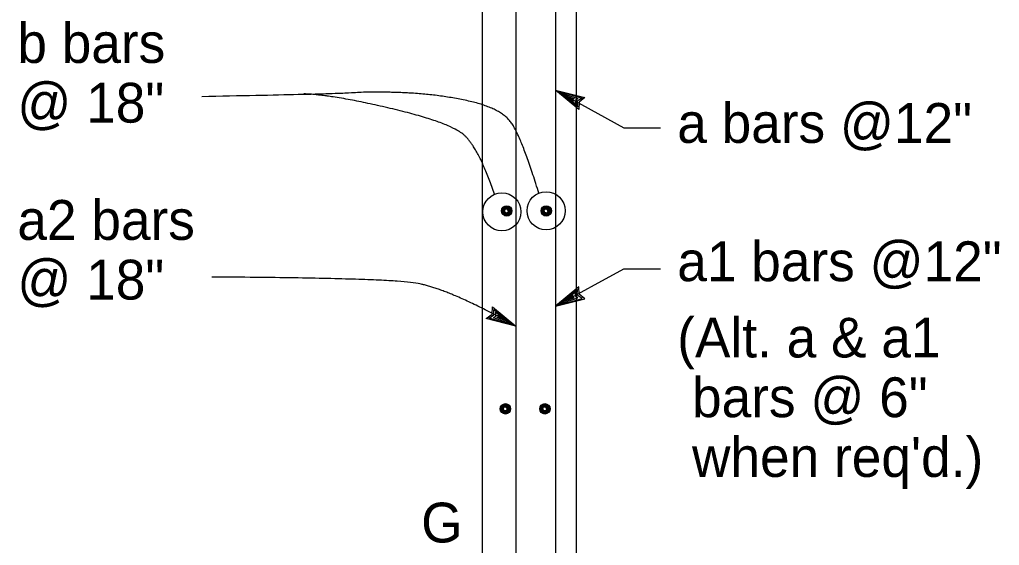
# Model space of a CAD drawing. Extents: x -0.08 to 2.83, y -0.03 to 1.92.
# Drawn here: x 1.1982 to 1.5188, y 0.4851 to 0.6571 of the extents above; entities that cross this region are included whole.
import ezdxf

# ---------------------------------------------------------------- set-up
doc = ezdxf.new("R2010")
doc.units = 0
for name, color, linetype in [('50', 7, 'Continuous'), ('51', 7, 'Continuous'), ('55', 7, 'Continuous'), ('57', 7, 'Continuous')]:
    doc.layers.add(name, color=color, linetype=linetype)

msp = doc.modelspace()

# ---------------------------------------------------------------- linework, layer by layer
at = {"layer": '50'}
for p, q in [((1.34968, 0.37752), (1.34968, 0.72906)), ((1.38033, 0.72906), (1.38033, 0.37752))]:
    msp.add_line(p, q, dxfattribs=at)
at = {"layer": '51'}
for p, q in [((1.36058, 0.72394), (1.36058, 0.4673)), ((1.37352, 0.72394), (1.37352, 0.50937)), ((1.37352, 0.50937), (1.37352, 0.46972))]:
    msp.add_line(p, q, dxfattribs=at)
for points in [[(1.356, 0.59466), (1.35622, 0.59531), (1.35668, 0.5958), (1.35727, 0.59607), (1.35784, 0.59607), (1.35829, 0.59593), (1.35866, 0.59564), (1.35896, 0.59523), (1.3591, 0.59483), (1.35914, 0.59428), (1.35903, 0.59376), (1.35876, 0.5934), (1.35833, 0.59308), (1.35784, 0.59291), (1.35722, 0.59291), (1.35673, 0.59316), (1.35637, 0.59346), (1.35617, 0.59379), (1.35604, 0.59419), (1.35605, 0.59457), (1.35619, 0.59496), (1.35638, 0.59534), (1.35668, 0.59566), (1.35696, 0.59586), (1.35723, 0.59596), (1.35751, 0.59598), (1.35789, 0.59598), (1.35821, 0.59586), (1.35847, 0.59564), (1.35869, 0.59545), (1.35889, 0.59515), (1.35899, 0.59477), (1.35903, 0.59438), (1.35898, 0.59405), (1.35886, 0.59367), (1.35871, 0.59348), (1.35844, 0.59329), (1.35819, 0.59313), (1.35789, 0.59304), (1.35754, 0.59299), (1.3571, 0.59311), (1.35673, 0.59329), (1.35644, 0.59354), (1.35622, 0.59398), (1.35615, 0.59438), (1.35624, 0.59477), (1.35641, 0.59515), (1.35667, 0.59551), (1.3569, 0.59572), (1.3572, 0.59583), (1.35759, 0.59588), (1.35795, 0.5958), (1.35821, 0.59566), (1.35851, 0.59539), (1.35875, 0.59504), (1.35884, 0.59468), (1.35887, 0.59428), (1.35883, 0.59395), (1.35861, 0.59354), (1.35833, 0.59332), (1.35801, 0.59321), (1.35758, 0.59313), (1.35713, 0.59324), (1.35679, 0.5934), (1.35655, 0.59362), (1.35638, 0.59392), (1.3563, 0.59419), (1.3563, 0.59455), (1.35641, 0.59483), (1.35654, 0.59509), (1.3567, 0.59531), (1.35696, 0.59561), (1.35725, 0.59574), (1.35759, 0.59577), (1.35788, 0.59569), (1.35826, 0.59541), (1.35851, 0.59509), (1.35869, 0.59471), (1.35871, 0.5943), (1.35864, 0.594), (1.35859, 0.59379), (1.35834, 0.59348), (1.35811, 0.59337), (1.35771, 0.59324), (1.35729, 0.59332), (1.35691, 0.59348), (1.35664, 0.5937), (1.35646, 0.59403), (1.35639, 0.59433), (1.35647, 0.59468), (1.35668, 0.59506), (1.35688, 0.59536), (1.3571, 0.59561), (1.35743, 0.59569), (1.35758, 0.59564), (1.35781, 0.59561), (1.35801, 0.59545), (1.35828, 0.59518), (1.35839, 0.59501), (1.35851, 0.59483), (1.35857, 0.59463)], [(1.35857, 0.59463), (1.35848, 0.59413), (1.35844, 0.59379), (1.35826, 0.59362), (1.35801, 0.59346), (1.35771, 0.5934), (1.35738, 0.5934), (1.35707, 0.59351), (1.35683, 0.5937), (1.35665, 0.59392), (1.35653, 0.59416), (1.35659, 0.59457), (1.35673, 0.59493), (1.35691, 0.59518), (1.35711, 0.59548), (1.3574, 0.59558), (1.35771, 0.59545), (1.35786, 0.59534), (1.35808, 0.59515), (1.35821, 0.59498), (1.35833, 0.59477), (1.35837, 0.59457), (1.35839, 0.59438), (1.35836, 0.59419), (1.35828, 0.59389), (1.35822, 0.59376), (1.35813, 0.59367), (1.35795, 0.59356), (1.35783, 0.59351), (1.35767, 0.59351), (1.35748, 0.59351), (1.35736, 0.59351), (1.3572, 0.59356), (1.35705, 0.59367), (1.35676, 0.59405), (1.35668, 0.59428), (1.3567, 0.59452), (1.35678, 0.59477), (1.35685, 0.59491), (1.35698, 0.59512), (1.3571, 0.59523), (1.35725, 0.59536), (1.35741, 0.59541), (1.35769, 0.59534), (1.35777, 0.59528), (1.35789, 0.59515), (1.35801, 0.59501), (1.35811, 0.59488), (1.35816, 0.59473), (1.35823, 0.59463), (1.35828, 0.59449), (1.35829, 0.59441), (1.35823, 0.59424), (1.35821, 0.59413), (1.35816, 0.59403), (1.35808, 0.59389), (1.35798, 0.59376), (1.35788, 0.5937), (1.35769, 0.59365), (1.35754, 0.59365), (1.35738, 0.59365), (1.35725, 0.59372), (1.3571, 0.59384), (1.35698, 0.59398), (1.35691, 0.59411), (1.35685, 0.59424), (1.35681, 0.59438), (1.3569, 0.59452), (1.35696, 0.59466), (1.35703, 0.59488), (1.35711, 0.59501), (1.35721, 0.59512), (1.35735, 0.59518), (1.35754, 0.59518), (1.35771, 0.59509), (1.35779, 0.59504), (1.35791, 0.59488), (1.35798, 0.59477), (1.35803, 0.59468), (1.35808, 0.59457), (1.35809, 0.59447), (1.35811, 0.59433), (1.35809, 0.59422), (1.35808, 0.59416), (1.35801, 0.59405), (1.35793, 0.594), (1.35789, 0.59395), (1.35786, 0.59389), (1.35781, 0.59384), (1.35771, 0.59381), (1.35762, 0.59381), (1.35748, 0.59384), (1.35738, 0.59384), (1.35727, 0.59389), (1.35717, 0.59395), (1.35707, 0.59403), (1.35703, 0.59411), (1.35702, 0.59422), (1.35698, 0.59435), (1.35696, 0.59444), (1.35702, 0.59455)], [(1.36894, 0.59466), (1.36916, 0.59531), (1.36962, 0.5958), (1.37021, 0.59607), (1.37078, 0.59607), (1.37123, 0.59593), (1.37161, 0.59564), (1.3719, 0.59523), (1.37205, 0.59483), (1.37209, 0.59428), (1.37197, 0.59376), (1.37171, 0.5934), (1.37127, 0.59308), (1.37078, 0.59291), (1.37017, 0.59291), (1.36968, 0.59316), (1.36931, 0.59346), (1.36911, 0.59379), (1.36898, 0.59419), (1.36899, 0.59457), (1.36914, 0.59496), (1.36932, 0.59534), (1.36962, 0.59566), (1.36991, 0.59586), (1.37018, 0.59596), (1.37046, 0.59598), (1.37083, 0.59598), (1.37115, 0.59586), (1.37141, 0.59564), (1.37163, 0.59545), (1.37183, 0.59515), (1.37194, 0.59477), (1.37197, 0.59438), (1.37193, 0.59405), (1.37181, 0.59367), (1.37166, 0.59348), (1.37138, 0.59329), (1.37114, 0.59313), (1.37083, 0.59304), (1.37048, 0.59299), (1.37004, 0.59311), (1.36968, 0.59329), (1.36939, 0.59354), (1.36916, 0.59398), (1.36909, 0.59438), (1.36919, 0.59477), (1.36935, 0.59515), (1.36961, 0.59551), (1.36984, 0.59572), (1.37014, 0.59583), (1.37054, 0.59588), (1.37089, 0.5958), (1.37115, 0.59566), (1.37145, 0.59539), (1.37169, 0.59504), (1.37179, 0.59468), (1.37182, 0.59428), (1.37178, 0.59395), (1.37156, 0.59354), (1.37127, 0.59332), (1.37096, 0.59321), (1.37052, 0.59313), (1.37008, 0.59324), (1.36974, 0.5934), (1.3695, 0.59362), (1.36932, 0.59392), (1.36924, 0.59419), (1.36924, 0.59455), (1.36935, 0.59483), (1.36949, 0.59509), (1.36965, 0.59531), (1.36991, 0.59561), (1.37019, 0.59574), (1.37054, 0.59577), (1.37083, 0.59569), (1.3712, 0.59541), (1.37145, 0.59509), (1.37163, 0.59471), (1.37166, 0.5943), (1.37159, 0.594), (1.37153, 0.59379), (1.37128, 0.59348), (1.37105, 0.59337), (1.37066, 0.59324), (1.37024, 0.59332), (1.36986, 0.59348), (1.36958, 0.5937), (1.3694, 0.59403), (1.36934, 0.59433), (1.36942, 0.59468), (1.36962, 0.59506), (1.36982, 0.59536), (1.37004, 0.59561), (1.37037, 0.59569), (1.37052, 0.59564), (1.37076, 0.59561), (1.37094, 0.59545), (1.37122, 0.59518), (1.37134, 0.59501), (1.37145, 0.59483), (1.37152, 0.59463)], [(1.37152, 0.59463), (1.37143, 0.59413), (1.37138, 0.59379), (1.3712, 0.59362), (1.37096, 0.59346), (1.37066, 0.5934), (1.37033, 0.5934), (1.37002, 0.59351), (1.36977, 0.5937), (1.3696, 0.59392), (1.36947, 0.59416), (1.36953, 0.59457), (1.36968, 0.59493), (1.36986, 0.59518), (1.37006, 0.59548), (1.37035, 0.59558), (1.37066, 0.59545), (1.3708, 0.59534), (1.37101, 0.59515), (1.37115, 0.59498), (1.37127, 0.59477), (1.37131, 0.59457), (1.37134, 0.59438), (1.3713, 0.59419), (1.37122, 0.59389), (1.37116, 0.59376), (1.37108, 0.59367), (1.37089, 0.59356), (1.37078, 0.59351), (1.37062, 0.59351), (1.37042, 0.59351), (1.3703, 0.59351), (1.37014, 0.59356), (1.36999, 0.59367), (1.36971, 0.59405), (1.36962, 0.59428), (1.36964, 0.59452), (1.36971, 0.59477), (1.36979, 0.59491), (1.36993, 0.59512), (1.37004, 0.59523), (1.37019, 0.59536), (1.37036, 0.59541), (1.37063, 0.59534), (1.37072, 0.59528), (1.37083, 0.59515), (1.37096, 0.59501), (1.37105, 0.59488), (1.37111, 0.59473), (1.37118, 0.59463), (1.37122, 0.59449), (1.37123, 0.59441), (1.37118, 0.59424), (1.37115, 0.59413), (1.37111, 0.59403), (1.37103, 0.59389), (1.37093, 0.59376), (1.37083, 0.5937), (1.37063, 0.59365), (1.37048, 0.59365), (1.37033, 0.59365), (1.37019, 0.59372), (1.37004, 0.59384), (1.36993, 0.59398), (1.36986, 0.59411), (1.36979, 0.59424), (1.36976, 0.59438), (1.36984, 0.59452), (1.36989, 0.59466), (1.36998, 0.59488), (1.37006, 0.59501), (1.37015, 0.59512), (1.37029, 0.59518), (1.37048, 0.59518), (1.37066, 0.59509), (1.37073, 0.59504), (1.37086, 0.59488), (1.37093, 0.59477), (1.37098, 0.59468), (1.37101, 0.59457), (1.37104, 0.59447), (1.37105, 0.59433), (1.37104, 0.59422), (1.37103, 0.59416), (1.37094, 0.59405), (1.37088, 0.594), (1.37083, 0.59395), (1.37081, 0.59389), (1.37076, 0.59384), (1.37066, 0.59381), (1.37057, 0.59381), (1.37042, 0.59384), (1.37032, 0.59384), (1.37021, 0.59389), (1.37012, 0.59395), (1.37002, 0.59403), (1.36998, 0.59411), (1.36997, 0.59422), (1.36993, 0.59435), (1.36991, 0.59444), (1.36997, 0.59455)], [(1.35558, 0.52993), (1.35579, 0.53059), (1.35626, 0.53108), (1.35685, 0.53135), (1.35741, 0.53135), (1.35786, 0.53121), (1.35823, 0.53092), (1.35853, 0.53051), (1.35869, 0.5301), (1.35872, 0.52955), (1.3586, 0.52904), (1.35834, 0.52868), (1.35791, 0.52836), (1.35741, 0.52819), (1.3568, 0.52819), (1.35631, 0.52843), (1.35594, 0.52874), (1.35574, 0.52907), (1.35561, 0.52947), (1.35563, 0.52986), (1.35577, 0.53023), (1.35596, 0.53061), (1.35626, 0.53094), (1.35654, 0.53113), (1.35681, 0.53124), (1.35709, 0.53127), (1.35747, 0.53127), (1.35779, 0.53113), (1.35804, 0.53092), (1.35826, 0.53072), (1.35847, 0.53043), (1.35857, 0.53004), (1.3586, 0.52966), (1.35856, 0.52933), (1.35844, 0.52895), (1.35829, 0.52876), (1.35801, 0.52857), (1.35777, 0.52841), (1.35747, 0.52832), (1.35711, 0.52827), (1.35668, 0.52838), (1.35631, 0.52857), (1.35602, 0.52882), (1.35579, 0.52925), (1.35573, 0.52966), (1.35582, 0.53004), (1.35599, 0.53043), (1.35624, 0.53077), (1.35647, 0.53099), (1.35678, 0.53111), (1.35717, 0.53116), (1.35753, 0.53108), (1.35779, 0.53094), (1.35808, 0.53067), (1.35833, 0.53031), (1.35842, 0.52996), (1.35845, 0.52955), (1.35841, 0.52923), (1.35819, 0.52882), (1.35791, 0.5286), (1.35759, 0.52848), (1.35716, 0.52841), (1.3567, 0.52852), (1.35637, 0.52868), (1.35613, 0.5289), (1.35596, 0.5292), (1.35587, 0.52947), (1.35587, 0.52982), (1.35599, 0.5301), (1.35612, 0.53037), (1.35628, 0.53059), (1.35654, 0.53089), (1.35683, 0.53102), (1.35717, 0.53105), (1.35746, 0.53097), (1.35784, 0.5307), (1.35808, 0.53037), (1.35826, 0.52999), (1.35829, 0.52958), (1.35822, 0.52928), (1.35816, 0.52907), (1.35791, 0.52876), (1.35769, 0.52865), (1.35729, 0.52852), (1.35687, 0.5286), (1.35649, 0.52876), (1.35622, 0.52897), (1.35604, 0.52931), (1.35597, 0.5296), (1.35605, 0.52996), (1.35626, 0.53034), (1.35646, 0.53064), (1.35668, 0.53089), (1.35701, 0.53097), (1.35716, 0.53092), (1.35738, 0.53089), (1.35758, 0.53072), (1.35786, 0.53045), (1.35798, 0.53028), (1.35808, 0.5301), (1.35815, 0.52991)], [(1.35815, 0.52991), (1.35806, 0.52942), (1.35801, 0.52907), (1.35784, 0.5289), (1.35759, 0.52874), (1.35729, 0.52868), (1.35696, 0.52868), (1.35665, 0.52879), (1.35641, 0.52897), (1.35623, 0.5292), (1.35611, 0.52944), (1.35617, 0.52986), (1.35631, 0.53021), (1.35649, 0.53045), (1.3567, 0.53075), (1.35698, 0.53087), (1.35729, 0.53072), (1.35743, 0.53061), (1.35764, 0.53043), (1.35779, 0.53026), (1.35791, 0.53004), (1.35795, 0.52986), (1.35798, 0.52966), (1.35793, 0.52947), (1.35786, 0.52917), (1.3578, 0.52904), (1.35771, 0.52895), (1.35753, 0.52885), (1.3574, 0.52879), (1.35725, 0.52879), (1.35706, 0.52879), (1.35694, 0.52879), (1.35678, 0.52885), (1.35662, 0.52895), (1.35634, 0.52933), (1.35626, 0.52955), (1.35628, 0.5298), (1.35635, 0.53004), (1.35643, 0.53017), (1.35655, 0.5304), (1.35668, 0.53051), (1.35683, 0.53064), (1.35699, 0.5307), (1.35727, 0.53061), (1.35735, 0.53056), (1.35747, 0.53043), (1.35759, 0.53028), (1.35769, 0.53015), (1.35774, 0.53002), (1.35781, 0.52991), (1.35786, 0.52977), (1.35786, 0.52969), (1.35781, 0.52952), (1.35779, 0.52942), (1.35774, 0.52931), (1.35766, 0.52917), (1.35756, 0.52904), (1.35746, 0.52897), (1.35727, 0.52892), (1.35711, 0.52892), (1.35696, 0.52892), (1.35683, 0.52901), (1.35668, 0.52912), (1.35655, 0.52925), (1.35649, 0.52939), (1.35643, 0.52952), (1.35639, 0.52966), (1.35647, 0.5298), (1.35653, 0.52993), (1.35662, 0.53015), (1.3567, 0.53028), (1.35679, 0.5304), (1.35693, 0.53045), (1.35711, 0.53045), (1.35729, 0.53037), (1.35736, 0.53031), (1.3575, 0.53015), (1.35756, 0.53004), (1.35761, 0.52996), (1.35764, 0.52986), (1.35767, 0.52975), (1.35769, 0.5296), (1.35767, 0.5295), (1.35766, 0.52944), (1.35758, 0.52933), (1.35751, 0.52928), (1.35747, 0.52923), (1.35744, 0.52917), (1.35738, 0.52912), (1.35729, 0.52909), (1.3572, 0.52909), (1.35706, 0.52912), (1.35696, 0.52912), (1.35685, 0.52917), (1.35674, 0.52923), (1.35665, 0.52931), (1.35662, 0.52939), (1.3566, 0.5295), (1.35655, 0.52963), (1.35654, 0.52972), (1.3566, 0.52982)], [(1.36852, 0.52993), (1.36874, 0.53059), (1.3692, 0.53108), (1.36979, 0.53135), (1.37036, 0.53135), (1.37081, 0.53121), (1.37118, 0.53092), (1.37148, 0.53051), (1.37163, 0.5301), (1.37167, 0.52955), (1.37154, 0.52904), (1.37128, 0.52868), (1.37085, 0.52836), (1.37036, 0.52819), (1.36974, 0.52819), (1.36926, 0.52843), (1.36889, 0.52874), (1.36869, 0.52907), (1.36856, 0.52947), (1.36857, 0.52986), (1.36872, 0.53023), (1.36891, 0.53061), (1.3692, 0.53094), (1.36949, 0.53113), (1.36976, 0.53124), (1.37004, 0.53127), (1.37041, 0.53127), (1.37073, 0.53113), (1.37099, 0.53092), (1.3712, 0.53072), (1.37141, 0.53043), (1.37152, 0.53004), (1.37154, 0.52966), (1.37151, 0.52933), (1.37138, 0.52895), (1.37123, 0.52876), (1.37096, 0.52857), (1.37072, 0.52841), (1.37041, 0.52832), (1.37006, 0.52827), (1.36962, 0.52838), (1.36926, 0.52857), (1.36897, 0.52882), (1.36874, 0.52925), (1.36867, 0.52966), (1.36877, 0.53004), (1.36893, 0.53043), (1.36919, 0.53077), (1.36942, 0.53099), (1.36971, 0.53111), (1.37012, 0.53116), (1.37047, 0.53108), (1.37073, 0.53094), (1.37103, 0.53067), (1.37127, 0.53031), (1.37136, 0.52996), (1.3714, 0.52955), (1.37136, 0.52923), (1.37114, 0.52882), (1.37085, 0.5286), (1.37054, 0.52848), (1.3701, 0.52841), (1.36965, 0.52852), (1.36931, 0.52868), (1.36908, 0.5289), (1.36891, 0.5292), (1.36882, 0.52947), (1.36882, 0.52982), (1.36893, 0.5301), (1.36906, 0.53037), (1.36923, 0.53059), (1.36949, 0.53089), (1.36977, 0.53102), (1.37012, 0.53105), (1.3704, 0.53097), (1.37078, 0.5307), (1.37103, 0.53037), (1.3712, 0.52999), (1.37123, 0.52958), (1.37116, 0.52928), (1.37111, 0.52907), (1.37086, 0.52876), (1.37063, 0.52865), (1.37024, 0.52852), (1.36982, 0.5286), (1.36943, 0.52876), (1.36916, 0.52897), (1.36898, 0.52931), (1.36892, 0.5296), (1.36899, 0.52996), (1.3692, 0.53034), (1.3694, 0.53064), (1.36962, 0.53089), (1.36995, 0.53097), (1.3701, 0.53092), (1.37033, 0.53089), (1.37052, 0.53072), (1.3708, 0.53045), (1.37092, 0.53028), (1.37103, 0.5301), (1.37109, 0.52991)], [(1.37109, 0.52991), (1.371, 0.52942), (1.37096, 0.52907), (1.37078, 0.5289), (1.37054, 0.52874), (1.37024, 0.52868), (1.36991, 0.52868), (1.3696, 0.52879), (1.36935, 0.52897), (1.36918, 0.5292), (1.36906, 0.52944), (1.36911, 0.52986), (1.36926, 0.53021), (1.36943, 0.53045), (1.36964, 0.53075), (1.36993, 0.53087), (1.37024, 0.53072), (1.37037, 0.53061), (1.37059, 0.53043), (1.37073, 0.53026), (1.37085, 0.53004), (1.37089, 0.52986), (1.37092, 0.52966), (1.37088, 0.52947), (1.3708, 0.52917), (1.37074, 0.52904), (1.37066, 0.52895), (1.37047, 0.52885), (1.37035, 0.52879), (1.37019, 0.52879), (1.37, 0.52879), (1.36989, 0.52879), (1.36971, 0.52885), (1.36956, 0.52895), (1.36929, 0.52933), (1.3692, 0.52955), (1.36921, 0.5298), (1.3693, 0.53004), (1.36938, 0.53017), (1.3695, 0.5304), (1.36962, 0.53051), (1.36977, 0.53064), (1.36994, 0.5307), (1.37021, 0.53061), (1.37029, 0.53056), (1.37041, 0.53043), (1.37054, 0.53028), (1.37063, 0.53015), (1.37068, 0.53002), (1.37076, 0.52991), (1.3708, 0.52977), (1.37081, 0.52969), (1.37076, 0.52952), (1.37073, 0.52942), (1.37068, 0.52931), (1.3706, 0.52917), (1.37051, 0.52904), (1.3704, 0.52897), (1.37021, 0.52892), (1.37006, 0.52892), (1.36991, 0.52892), (1.36977, 0.52901), (1.36962, 0.52912), (1.3695, 0.52925), (1.36943, 0.52939), (1.36938, 0.52952), (1.36934, 0.52966), (1.36942, 0.5298), (1.36947, 0.52993), (1.36956, 0.53015), (1.36964, 0.53028), (1.36974, 0.5304), (1.36987, 0.53045), (1.37006, 0.53045), (1.37024, 0.53037), (1.3703, 0.53031), (1.37044, 0.53015), (1.37051, 0.53004), (1.37055, 0.52996), (1.37059, 0.52986), (1.37062, 0.52975), (1.37063, 0.5296), (1.37062, 0.5295), (1.3706, 0.52944), (1.37052, 0.52933), (1.37046, 0.52928), (1.37041, 0.52923), (1.37039, 0.52917), (1.37033, 0.52912), (1.37024, 0.52909), (1.37014, 0.52909), (1.37, 0.52912), (1.36989, 0.52912), (1.36979, 0.52917), (1.36969, 0.52923), (1.3696, 0.52931), (1.36956, 0.52939), (1.36954, 0.5295), (1.3695, 0.52963), (1.36949, 0.52972), (1.36954, 0.52982)]]:
    msp.add_lwpolyline(points, dxfattribs=at)
for centre in [(1.35761, 0.5945), (1.37055, 0.5945), (1.35719, 0.52978), (1.37013, 0.52978)]:
    msp.add_circle(centre, 0.0017, dxfattribs=at)
at = {"layer": '55'}
for p, q in [((1.37352, 0.63394), (1.39597, 0.62172)), ((1.37352, 0.63394), (1.38319, 0.63158)), ((1.38125, 0.62767), (1.37352, 0.63394)), ((1.37352, 0.63394), (1.38225, 0.63141)), ((1.38074, 0.62854), (1.37466, 0.63338)), ((1.37466, 0.63338), (1.38083, 0.63125)), ((1.38008, 0.62943), (1.37624, 0.63244)), ((1.37624, 0.63244), (1.3797, 0.63119)), ((1.37933, 0.63044), (1.37781, 0.63166)), ((1.37781, 0.63166), (1.37863, 0.63125)), ((1.38319, 0.63158), (1.38127, 0.63008)), ((1.3797, 0.63119), (1.37892, 0.63119)), ((1.37892, 0.63119), (1.37933, 0.63044)), ((1.38014, 0.63065), (1.38008, 0.62943)), ((1.38083, 0.63125), (1.38014, 0.63065)), ((1.38225, 0.63141), (1.38071, 0.63036)), ((1.38071, 0.63036), (1.38074, 0.62854)), ((1.38127, 0.63008), (1.38125, 0.62767)), ((1.39597, 0.62172), (1.40792, 0.62172)), ((1.37352, 0.56336), (1.39597, 0.57558)), ((1.39597, 0.57558), (1.40792, 0.57558)), ((1.38125, 0.56963), (1.37352, 0.56336)), ((1.38074, 0.56876), (1.37466, 0.56393)), ((1.38008, 0.56788), (1.37624, 0.56486)), ((1.38014, 0.56665), (1.38008, 0.56788)), ((1.38071, 0.56694), (1.38074, 0.56876)), ((1.38127, 0.56722), (1.38125, 0.56963)), ((1.37352, 0.56336), (1.38225, 0.56589)), ((1.37352, 0.56336), (1.38319, 0.56573)), ((1.37466, 0.56393), (1.38083, 0.56605)), ((1.37624, 0.56486), (1.3797, 0.56611)), ((1.37933, 0.56686), (1.37781, 0.56564)), ((1.37781, 0.56564), (1.37863, 0.56605)), ((1.37892, 0.56611), (1.37933, 0.56686)), ((1.3797, 0.56611), (1.37892, 0.56611)), ((1.38083, 0.56605), (1.38014, 0.56665)), ((1.38225, 0.56589), (1.38071, 0.56694)), ((1.38319, 0.56573), (1.38127, 0.56722)), ((1.35288, 0.56075), (1.35292, 0.56317)), ((1.35292, 0.56317), (1.36058, 0.55681)), ((1.35344, 0.56046), (1.35342, 0.56229)), ((1.35342, 0.56229), (1.35945, 0.55739)), ((1.354, 0.56018), (1.35407, 0.5614)), ((1.35407, 0.5614), (1.35788, 0.55834)), ((1.35093, 0.55928), (1.35288, 0.56075)), ((1.36058, 0.55681), (1.35093, 0.55928)), ((1.35188, 0.55943), (1.35344, 0.56046)), ((1.36058, 0.55681), (1.35188, 0.55943)), ((1.3533, 0.55958), (1.354, 0.56018)), ((1.35945, 0.55739), (1.3533, 0.55958)), ((1.35788, 0.55834), (1.35443, 0.55963)), ((1.35443, 0.55963), (1.35522, 0.55962)), ((1.35522, 0.55962), (1.35482, 0.56038)), ((1.35482, 0.56038), (1.35632, 0.55914)), ((1.35632, 0.55914), (1.3555, 0.55956))]:
    msp.add_line(p, q, dxfattribs=at)
for centre in [(1.35603, 0.5942), (1.3705, 0.59453)]:
    msp.add_circle(centre, 0.00624, dxfattribs=at)
for points in [[(1.36814, 0.60027), (1.36261, 0.6182), (1.35596, 0.62802), (1.33493, 0.63271), (1.3128, 0.63357), (1.30284, 0.63271), (1.25782, 0.63186)], [(1.35361, 0.59997), (1.34826, 0.61578), (1.33803, 0.62369), (1.30103, 0.63238), (1.29129, 0.63278)], [(1.36058, 0.55681), (1.33799, 0.56942), (1.31679, 0.5725), (1.26113, 0.57288)]]:
    msp.add_open_spline(points, degree=2, dxfattribs=at)

# ---------------------------------------------------------------- texts
at = {"layer": '57'}
for s, height, p in [('b bars', 0.013021, (1.19751, 0.6429)), ('@ 18"', 0.013021, (1.19751, 0.62337)), ('a bars @12"', 0.0130208, (1.4134, 0.61675)), ('a2 bars', 0.013021, (1.19751, 0.58504)), ('a1 bars @12"', 0.0130208, (1.4134, 0.57152)), ('@ 18"', 0.013021, (1.19751, 0.56551)), ('(Alt. a & a1', 0.0130208, (1.4134, 0.54657)), (' bars @ 6"', 0.013021, (1.4134, 0.52704)), (" when req'd.)", 0.0130208, (1.4134, 0.50751)), ('G', 0.01302, (1.32963, 0.48606))]:
    msp.add_text(s, height=height, dxfattribs=at).set_placement(p)

doc.saveas('drawing.dxf')
